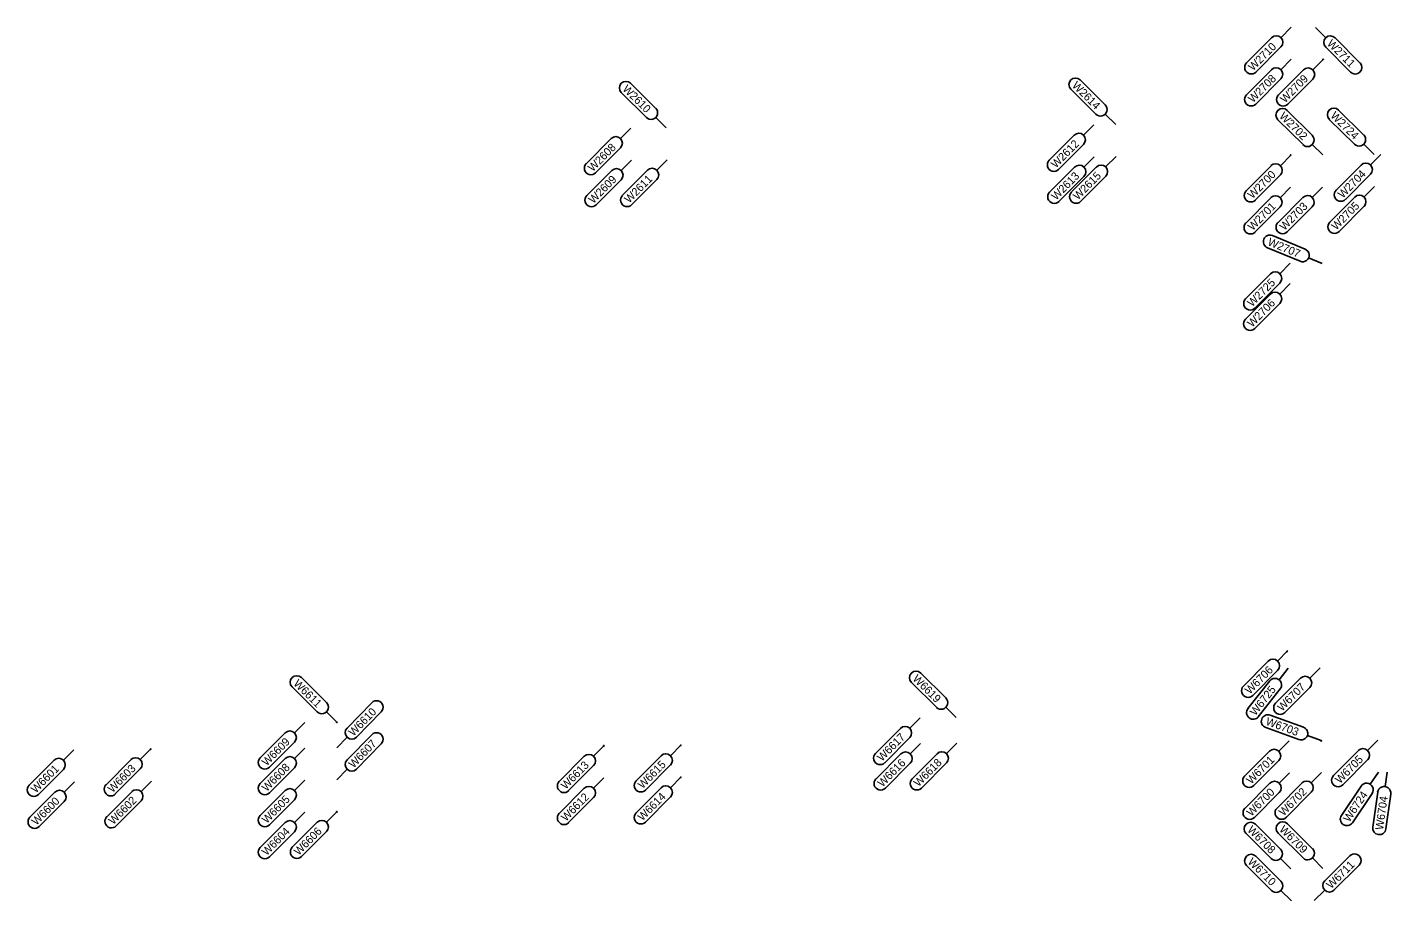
# Model space of a CAD drawing. Extents: x 12479652 to 12487250, y 9842710 to 9846560.
# Drawn here: x 12484406.3 to 12484619.2, y 9842741.1 to 9842877.6 of the extents above; entities that cross this region are included whole.
import ezdxf

# ---------------------------------------------------------------- set-up
doc = ezdxf.new("R2010")
doc.units = 0
doc.layers.add('_CIVIL_CONSTRUCTION', color=7, linetype='Continuous')
doc.layers.add('TextAlignmentLrg', color=7, linetype='Continuous')

msp = doc.modelspace()

# ---------------------------------------------------------------- linework, layer by layer
at = {"layer": '_CIVIL_CONSTRUCTION'}
for p, q in [((12484603.7, 9842877.64), (12484602.07, 9842876.01)), ((12484607.47, 9842877.63), (12484609.09, 9842876)), ((12484596.73, 9842872.1), (12484600.62, 9842876.01)), ((12484602.08, 9842874.56), (12484598.19, 9842870.65)), ((12484609.08, 9842874.55), (12484612.97, 9842870.63)), ((12484614.43, 9842872.08), (12484610.54, 9842875.99)), ((12484603.67, 9842872.65), (12484602.05, 9842871.01)), ((12484608.67, 9842872.62), (12484607.05, 9842870.99)), ((12484596.71, 9842867.1), (12484600.6, 9842871.01)), ((12484601.71, 9842867.07), (12484605.6, 9842870.99)), ((12484500.53, 9842868.89), (12484504.44, 9842865)), ((12484570.73, 9842869.41), (12484574.64, 9842865.52)), ((12484602.06, 9842869.56), (12484598.17, 9842865.65)), ((12484607.06, 9842869.54), (12484603.17, 9842865.63)), ((12484503, 9842863.54), (12484499.08, 9842867.43)), ((12484573.19, 9842864.06), (12484569.28, 9842867.95)), ((12484576.28, 9842862.45), (12484574.65, 9842864.07)), ((12484603.06, 9842864.65), (12484606.97, 9842860.76)), ((12484611.09, 9842864.71), (12484615, 9842860.82)), ((12484500.58, 9842861.88), (12484498.96, 9842860.25)), ((12484506.08, 9842861.93), (12484504.45, 9842863.55)), ((12484572.87, 9842862.42), (12484571.25, 9842860.79)), ((12484605.53, 9842859.3), (12484601.61, 9842863.19)), ((12484613.56, 9842859.36), (12484609.64, 9842863.25)), ((12484493.62, 9842856.34), (12484497.51, 9842860.25)), ((12484565.91, 9842856.87), (12484569.8, 9842860.78)), ((12484498.96, 9842858.8), (12484495.07, 9842854.89)), ((12484571.26, 9842859.34), (12484567.37, 9842855.42)), ((12484572.93, 9842857.42), (12484571.31, 9842855.79)), ((12484576.33, 9842857.44), (12484574.71, 9842855.81)), ((12484603.61, 9842857.65), (12484601.99, 9842856.01)), ((12484608.61, 9842857.69), (12484606.98, 9842859.31)), ((12484616.64, 9842857.75), (12484615.01, 9842859.37)), ((12484617.69, 9842857.75), (12484616.06, 9842856.12)), ((12484493.71, 9842851.34), (12484497.6, 9842855.25)), ((12484500.68, 9842856.88), (12484499.06, 9842855.25)), ((12484499.27, 9842851.38), (12484503.16, 9842855.29)), ((12484506.23, 9842856.93), (12484504.61, 9842855.29)), ((12484565.97, 9842851.87), (12484569.86, 9842855.78)), ((12484569.37, 9842851.9), (12484573.26, 9842855.81)), ((12484596.65, 9842852.1), (12484600.54, 9842856.01)), ((12484610.72, 9842852.2), (12484614.61, 9842856.11)), ((12484499.06, 9842853.8), (12484495.17, 9842849.89)), ((12484504.62, 9842853.84), (12484500.73, 9842849.93)), ((12484571.31, 9842854.34), (12484567.42, 9842850.42)), ((12484574.72, 9842854.36), (12484570.83, 9842850.45)), ((12484601.99, 9842854.56), (12484598.1, 9842850.65)), ((12484616.07, 9842854.67), (12484612.18, 9842850.75)), ((12484596.63, 9842847.1), (12484600.52, 9842851.01)), ((12484601.63, 9842847.13), (12484605.52, 9842851.05)), ((12484603.59, 9842852.64), (12484601.97, 9842851.01)), ((12484608.59, 9842852.68), (12484606.97, 9842851.05)), ((12484609.71, 9842847.19), (12484613.6, 9842851.11)), ((12484616.67, 9842852.74), (12484615.05, 9842851.11)), ((12484601.97, 9842849.56), (12484598.08, 9842845.65)), ((12484606.97, 9842849.6), (12484603.08, 9842845.69)), ((12484615.06, 9842849.66), (12484611.17, 9842845.75)), ((12484600.77, 9842845.08), (12484605.86, 9842842.96)), ((12484605.07, 9842841.07), (12484599.98, 9842843.19)), ((12484603.53, 9842840.76), (12484601.91, 9842839.13)), ((12484608.54, 9842840.74), (12484606.41, 9842841.62)), ((12484596.57, 9842835.21), (12484600.46, 9842839.12)), ((12484601.92, 9842837.67), (12484598.03, 9842833.76)), ((12484603.53, 9842837.58), (12484601.9, 9842835.95)), ((12484596.56, 9842832.03), (12484600.45, 9842835.95)), ((12484601.91, 9842834.5), (12484598.02, 9842830.59)), ((12484596.22, 9842774.68), (12484600.11, 9842778.6)), ((12484603.18, 9842780.23), (12484601.56, 9842778.6)), ((12484545.83, 9842776.72), (12484549.74, 9842772.83)), ((12484601.56, 9842777.15), (12484597.67, 9842773.24)), ((12484603.22, 9842777.48), (12484601.79, 9842775.68)), ((12484608.22, 9842777.55), (12484606.6, 9842775.92)), ((12484451.58, 9842770.66), (12484447.67, 9842774.55)), ((12484449.12, 9842776.01), (12484453.03, 9842772.12)), ((12484548.3, 9842771.38), (12484544.39, 9842775.27)), ((12484596.94, 9842771.17), (12484600.35, 9842775.51)), ((12484601.26, 9842772), (12484605.15, 9842775.92)), ((12484606.6, 9842774.47), (12484602.71, 9842770.56)), ((12484601.97, 9842774.24), (12484598.55, 9842769.9)), ((12484454.66, 9842769.04), (12484453.03, 9842770.67)), ((12484460.11, 9842772.08), (12484456.26, 9842768.14)), ((12484457.72, 9842766.7), (12484461.58, 9842770.65)), ((12484551.38, 9842769.76), (12484549.75, 9842771.38)), ((12484600.4, 9842770.15), (12484605.59, 9842768.27)), ((12484449.66, 9842769.01), (12484448.04, 9842767.38)), ((12484538.77, 9842764.17), (12484542.66, 9842768.08)), ((12484545.73, 9842769.72), (12484544.11, 9842768.09)), ((12484604.89, 9842766.34), (12484599.7, 9842768.22)), ((12484442.7, 9842763.46), (12484446.59, 9842767.37)), ((12484448.05, 9842765.93), (12484444.16, 9842762.01)), ((12484454.66, 9842765.04), (12484456.27, 9842766.69)), ((12484460.11, 9842767.08), (12484456.26, 9842763.14)), ((12484544.12, 9842766.63), (12484540.23, 9842762.72)), ((12484603.37, 9842766.14), (12484601.75, 9842764.51)), ((12484608.37, 9842766.18), (12484606.21, 9842766.96)), ((12484617.24, 9842766.25), (12484615.62, 9842764.61)), ((12484413.58, 9842764.74), (12484411.96, 9842763.11)), ((12484425.58, 9842764.83), (12484423.96, 9842763.2)), ((12484449.66, 9842765.01), (12484448.04, 9842763.38)), ((12484457.72, 9842761.7), (12484461.58, 9842765.65)), ((12484489.4, 9842759.8), (12484493.29, 9842763.72)), ((12484496.36, 9842765.35), (12484494.74, 9842763.72)), ((12484501.4, 9842759.89), (12484505.29, 9842763.81)), ((12484508.36, 9842765.44), (12484506.74, 9842763.81)), ((12484538.85, 9842760.17), (12484542.74, 9842764.08)), ((12484545.82, 9842765.72), (12484544.19, 9842764.09)), ((12484544.5, 9842760.21), (12484548.39, 9842764.12)), ((12484551.46, 9842765.76), (12484549.84, 9842764.13)), ((12484596.41, 9842760.59), (12484600.3, 9842764.51)), ((12484610.28, 9842760.7), (12484614.17, 9842764.61)), ((12484406.62, 9842759.19), (12484410.51, 9842763.1)), ((12484411.96, 9842761.66), (12484408.07, 9842757.75)), ((12484418.62, 9842759.28), (12484422.51, 9842763.19)), ((12484423.96, 9842761.75), (12484420.07, 9842757.83)), ((12484442.7, 9842759.46), (12484446.59, 9842763.37)), ((12484448.05, 9842761.92), (12484444.16, 9842758.01)), ((12484454.66, 9842760.04), (12484456.27, 9842761.69)), ((12484494.74, 9842762.27), (12484490.85, 9842758.36)), ((12484506.74, 9842762.36), (12484502.85, 9842758.45)), ((12484544.2, 9842762.64), (12484540.31, 9842758.72)), ((12484549.85, 9842762.68), (12484545.96, 9842758.76)), ((12484601.75, 9842763.06), (12484597.86, 9842759.15)), ((12484615.62, 9842763.16), (12484611.74, 9842759.25)), ((12484413.7, 9842759.74), (12484412.08, 9842758.11)), ((12484425.7, 9842759.83), (12484424.08, 9842758.2)), ((12484449.66, 9842760.01), (12484448.04, 9842758.38)), ((12484496.36, 9842760.35), (12484494.74, 9842758.72)), ((12484508.36, 9842760.44), (12484506.74, 9842758.81)), ((12484596.48, 9842755.59), (12484600.36, 9842759.51)), ((12484601.48, 9842755.63), (12484605.36, 9842759.54)), ((12484603.44, 9842761.14), (12484601.82, 9842759.51)), ((12484608.44, 9842761.18), (12484606.82, 9842759.55)), ((12484617.32, 9842761.25), (12484616.03, 9842759.34)), ((12484618.66, 9842761.26), (12484618.34, 9842758.98)), ((12484406.74, 9842754.19), (12484410.63, 9842758.11)), ((12484418.74, 9842754.28), (12484422.63, 9842758.19)), ((12484442.7, 9842754.46), (12484446.59, 9842758.37)), ((12484489.4, 9842754.8), (12484493.29, 9842758.72)), ((12484494.74, 9842757.27), (12484490.85, 9842753.36)), ((12484501.4, 9842754.89), (12484505.29, 9842758.8)), ((12484506.74, 9842757.36), (12484502.85, 9842753.45)), ((12484601.82, 9842758.06), (12484597.93, 9842754.15)), ((12484606.82, 9842758.1), (12484602.93, 9842754.19)), ((12484611.53, 9842754.48), (12484614.61, 9842759.06)), ((12484616.31, 9842757.91), (12484613.24, 9842753.33)), ((12484616.43, 9842752.64), (12484617.19, 9842758.1)), ((12484619.22, 9842757.82), (12484618.47, 9842752.36)), ((12484412.08, 9842756.66), (12484408.19, 9842752.75)), ((12484424.08, 9842756.75), (12484420.2, 9842752.83)), ((12484448.05, 9842756.92), (12484444.16, 9842753.01)), ((12484442.7, 9842749.46), (12484446.59, 9842753.37)), ((12484447.7, 9842749.5), (12484451.59, 9842753.41)), ((12484449.66, 9842755.01), (12484448.04, 9842753.38)), ((12484454.66, 9842755.04), (12484453.04, 9842753.41)), ((12484598.09, 9842753.11), (12484602, 9842749.22)), ((12484603.09, 9842753.17), (12484607, 9842749.28)), ((12484448.05, 9842751.92), (12484444.16, 9842748.01)), ((12484453.05, 9842751.96), (12484449.16, 9842748.05)), ((12484600.56, 9842747.76), (12484596.64, 9842751.65)), ((12484605.56, 9842747.83), (12484601.64, 9842751.72)), ((12484600.62, 9842742.76), (12484596.71, 9842746.65)), ((12484598.16, 9842748.11), (12484602.07, 9842744.22)), ((12484603.64, 9842746.14), (12484602.01, 9842747.77)), ((12484608.64, 9842746.21), (12484607.01, 9842747.83)), ((12484612.84, 9842748.16), (12484608.93, 9842744.27)), ((12484610.37, 9842742.81), (12484614.29, 9842746.7)), ((12484603.71, 9842741.14), (12484602.07, 9842742.77)), ((12484607.29, 9842741.19), (12484608.92, 9842742.81))]:
    msp.add_line(p, q, dxfattribs=at)
for centre, start, end in [((12484601.35, 9842875.29), 315.1702, 135.1702), ((12484609.81, 9842875.27), 44.8298, 224.8298), ((12484597.46, 9842871.37), 135.1702, 315.1702), ((12484601.33, 9842870.29), 315.1702, 135.1702), ((12484606.33, 9842870.26), 315.1702, 135.1702), ((12484613.7, 9842871.36), 224.8298, 44.8298), ((12484499.81, 9842868.16), 45.1702, 225.1702), ((12484570, 9842868.68), 45.1702, 225.1702), ((12484597.44, 9842866.37), 135.1702, 315.1702), ((12484602.44, 9842866.35), 135.1702, 315.1702), ((12484503.72, 9842864.27), 225.1702, 45.1702), ((12484573.92, 9842864.79), 225.1702, 45.1702), ((12484602.34, 9842863.92), 45.1702, 225.1702), ((12484610.37, 9842863.98), 45.1702, 225.1702), ((12484498.23, 9842859.53), 315.1702, 135.1702), ((12484570.53, 9842860.06), 315.1702, 135.1702), ((12484606.25, 9842860.03), 225.1702, 45.1702), ((12484614.28, 9842860.09), 225.1702, 45.1702), ((12484494.34, 9842855.61), 135.1702, 315.1702), ((12484498.33, 9842854.53), 315.1702, 135.1702), ((12484503.89, 9842854.57), 315.1702, 135.1702), ((12484566.64, 9842856.15), 135.1702, 315.1702), ((12484570.59, 9842855.06), 315.1702, 135.1702), ((12484573.99, 9842855.08), 315.1702, 135.1702), ((12484601.26, 9842855.29), 315.1702, 135.1702), ((12484615.34, 9842855.39), 315.1702, 135.1702), ((12484494.44, 9842850.61), 135.1702, 315.1702), ((12484500, 9842850.65), 135.1702, 315.1702), ((12484566.7, 9842851.15), 135.1702, 315.1702), ((12484570.1, 9842851.17), 135.1702, 315.1702), ((12484597.38, 9842851.37), 135.1702, 315.1702), ((12484601.24, 9842850.29), 315.1702, 135.1702), ((12484606.24, 9842850.32), 315.1702, 135.1702), ((12484611.45, 9842851.48), 135.1702, 315.1702), ((12484614.33, 9842850.38), 315.1702, 135.1702), ((12484597.35, 9842846.37), 135.1702, 315.1702), ((12484602.35, 9842846.41), 135.1702, 315.1702), ((12484610.44, 9842846.47), 135.1702, 315.1702), ((12484600.37, 9842844.14), 67.3935, 247.3935), ((12484605.47, 9842842.02), 247.3935, 67.3935), ((12484601.19, 9842838.4), 315.1702, 135.1702), ((12484601.18, 9842835.22), 315.1702, 135.1702), ((12484597.3, 9842834.48), 135.1702, 315.1702), ((12484597.29, 9842831.31), 135.1702, 315.1702), ((12484600.84, 9842777.87), 315.1702, 135.1702), ((12484545.11, 9842775.99), 45.1702, 225.1702), ((12484448.39, 9842775.28), 45.1702, 225.1702), ((12484596.95, 9842773.96), 135.1702, 315.1702), ((12484601.16, 9842774.87), 321.7716, 141.7716), ((12484605.87, 9842775.19), 315.1702, 135.1702), ((12484460.85, 9842771.37), 315.633, 135.633), ((12484549.02, 9842772.1), 225.1702, 45.1702), ((12484452.31, 9842771.39), 225.1702, 45.1702), ((12484597.75, 9842770.54), 141.7716, 321.7716), ((12484600.05, 9842769.18), 70.1575, 250.1575), ((12484601.98, 9842771.28), 135.1702, 315.1702), ((12484456.99, 9842767.42), 135.633, 315.633), ((12484543.39, 9842767.36), 315.1702, 135.1702), ((12484605.24, 9842767.31), 250.1575, 70.1575), ((12484447.32, 9842766.65), 315.1702, 135.1702), ((12484460.85, 9842766.37), 315.633, 135.633), ((12484447.32, 9842762.65), 315.1702, 135.1702), ((12484494.02, 9842762.99), 315.1702, 135.1702), ((12484506.02, 9842763.08), 315.1702, 135.1702), ((12484539.5, 9842763.45), 135.1702, 315.1702), ((12484543.47, 9842763.36), 315.1702, 135.1702), ((12484549.12, 9842763.4), 315.1702, 135.1702), ((12484601.03, 9842763.78), 315.1702, 135.1702), ((12484614.9, 9842763.89), 315.1702, 135.1702), ((12484411.23, 9842762.38), 315.1702, 135.1702), ((12484423.24, 9842762.47), 315.1702, 135.1702), ((12484443.43, 9842762.74), 135.1702, 315.1702), ((12484456.99, 9842762.42), 135.633, 315.633), ((12484443.43, 9842758.74), 135.1702, 315.1702), ((12484490.13, 9842759.08), 135.1702, 315.1702), ((12484502.13, 9842759.17), 135.1702, 315.1702), ((12484539.58, 9842759.45), 135.1702, 315.1702), ((12484545.23, 9842759.49), 135.1702, 315.1702), ((12484597.14, 9842759.87), 135.1702, 315.1702), ((12484601.09, 9842758.78), 315.1702, 135.1702), ((12484606.09, 9842758.82), 315.1702, 135.1702), ((12484611.01, 9842759.97), 135.1702, 315.1702), ((12484615.46, 9842758.49), 326.0823, 146.0823), ((12484407.34, 9842758.47), 135.1702, 315.1702), ((12484411.36, 9842757.38), 315.1702, 135.1702), ((12484419.35, 9842758.56), 135.1702, 315.1702), ((12484423.36, 9842757.47), 315.1702, 135.1702), ((12484447.32, 9842757.65), 315.1702, 135.1702), ((12484494.02, 9842757.99), 315.1702, 135.1702), ((12484506.02, 9842758.08), 315.1702, 135.1702), ((12484618.2, 9842757.96), 352.157, 172.157), ((12484597.2, 9842754.87), 135.1702, 315.1702), ((12484602.2, 9842754.91), 135.1702, 315.1702), ((12484407.47, 9842753.47), 135.1702, 315.1702), ((12484419.47, 9842753.56), 135.1702, 315.1702), ((12484443.43, 9842753.74), 135.1702, 315.1702), ((12484447.32, 9842752.65), 315.1702, 135.1702), ((12484452.32, 9842752.68), 315.1702, 135.1702), ((12484490.13, 9842754.08), 135.1702, 315.1702), ((12484502.13, 9842754.17), 135.1702, 315.1702), ((12484597.37, 9842752.38), 45.1702, 225.1702), ((12484602.37, 9842752.45), 45.1702, 225.1702), ((12484612.38, 9842753.91), 146.0823, 326.0823), ((12484617.45, 9842752.5), 172.157, 352.157), ((12484443.43, 9842748.74), 135.1702, 315.1702), ((12484448.43, 9842748.77), 135.1702, 315.1702), ((12484601.28, 9842748.49), 225.1702, 45.1702), ((12484606.28, 9842748.56), 225.1702, 45.1702), ((12484597.43, 9842747.38), 45.1702, 225.1702), ((12484613.56, 9842747.43), 314.8298, 134.8298), ((12484601.35, 9842743.49), 225.1702, 45.1702), ((12484609.65, 9842743.54), 134.8298, 314.8298)]:
    msp.add_arc(centre, 1.03, start, end, dxfattribs=at)
at = {"layer": 'TextAlignmentLrg'}
for centre in [(12484608.68, 9842872.63), (12484603.61, 9842857.65), (12484603.04, 9842780.09), (12484454.66, 9842769.04), (12484608.37, 9842766.13), (12484425.58, 9842764.83), (12484496.36, 9842765.35), (12484508.36, 9842765.44), (12484508.36, 9842760.44), (12484454.66, 9842755.04)]:
    msp.add_circle(centre, 0.05, dxfattribs=at)

# ---------------------------------------------------------------- texts
at = {"layer": '_CIVIL_CONSTRUCTION'}
for s, rotation, p in [('W2710', 45.1702, (12484597.73, 9842870.74)), ('W2711', 314.8298, (12484609.19, 9842874.99)), ('W2708', 45.1702, (12484597.71, 9842865.75)), ('W2709', 45.1702, (12484602.71, 9842865.73)), ('W2610', 315.1702, (12484499.18, 9842867.89)), ('W2614', 315.1702, (12484569.37, 9842868.42)), ('W2702', 315.1702, (12484601.73, 9842863.63)), ('W2724', 315.1702, (12484609.73, 9842863.72)), ('W2612', 45.1702, (12484566.93, 9842855.54)), ('W2608', 45.1702, (12484494.62, 9842854.99)), ('W2700', 45.1702, (12484597.65, 9842850.75)), ('W2704', 45.1702, (12484611.72, 9842850.84)), ('W2609', 45.1702, (12484494.72, 9842849.99)), ('W2611', 45.1702, (12484500.31, 9842850.06)), ('W2613', 45.1702, (12484566.98, 9842850.53)), ('W2615', 45.1702, (12484570.38, 9842850.56)), ('W2701', 45.1702, (12484597.66, 9842845.78)), ('W2703', 45.1702, (12484602.63, 9842845.79)), ('W2705', 45.1702, (12484610.72, 9842845.85)), ('W2707', 337.3935, (12484599.91, 9842843.64)), ('W2725', 45.1702, (12484597.58, 9842833.87)), ('W2706', 45.1702, (12484597.56, 9842830.68)), ('W6619', 315.1702, (12484544.48, 9842775.72)), ('W6706', 45.1702, (12484597.22, 9842773.33)), ('W6611', 315.1702, (12484447.8, 9842774.97)), ('W6725', 51.7716, (12484598.1, 9842769.96)), ('W6707', 45.1702, (12484602.27, 9842770.66)), ('W6610', 45.633, (12484457.24, 9842766.77)), ('W6703', 340.1575, (12484599.61, 9842768.67)), ('W6609', 45.1702, (12484443.7, 9842762.11)), ('W6607', 45.633, (12484457.26, 9842761.79)), ('W6617', 45.1702, (12484539.78, 9842762.83)), ('W6701', 45.1702, (12484597.44, 9842759.28)), ('W6705', 45.1702, (12484611.29, 9842759.36)), ('W6601', 45.1702, (12484407.65, 9842757.88)), ('W6603', 45.1702, (12484419.63, 9842757.94)), ('W6608', 45.1702, (12484443.7, 9842758.11)), ('W6613', 45.1702, (12484490.4, 9842758.46)), ('W6615', 45.1702, (12484502.41, 9842758.55)), ('W6616', 45.1702, (12484539.85, 9842758.82)), ('W6618', 45.1702, (12484545.5, 9842758.86)), ('W6600', 45.1702, (12484407.74, 9842752.84)), ('W6602', 45.1702, (12484419.76, 9842752.95)), ('W6605', 45.1702, (12484443.71, 9842753.12)), ('W6612', 45.1702, (12484490.42, 9842753.47)), ('W6614', 45.1702, (12484502.39, 9842753.53)), ('W6700', 45.1702, (12484597.47, 9842754.24)), ('W6702', 45.1702, (12484602.49, 9842754.3)), ('W6724', 56.0823, (12484612.76, 9842753.33)), ('W6704', 82.157, (12484618.04, 9842752.15)), ('W6709', 315.1702, (12484601.74, 9842752.17)), ('W6604', 45.1702, (12484443.69, 9842748.1)), ('W6606', 45.1702, (12484448.7, 9842748.14)), ('W6708', 315.1702, (12484596.74, 9842752.11)), ('W6710', 315.1702, (12484596.81, 9842747.11)), ('W6711', 44.8298, (12484609.93, 9842742.92))]:
    msp.add_text(s, height=1.25, rotation=rotation, dxfattribs=at).set_placement(p)

doc.saveas('drawing.dxf')
